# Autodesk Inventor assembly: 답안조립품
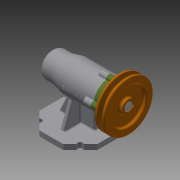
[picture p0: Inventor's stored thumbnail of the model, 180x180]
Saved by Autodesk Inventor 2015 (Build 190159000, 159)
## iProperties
Created: 2019-12
Part Number: 답안조립품
Document SubType Name: Assembly
Designer: 101548
Author: 101548
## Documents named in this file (12)
- C:\Users\101548\Desktop\491204V1047\답안조립품.iam
- C:\Users\101548\Desktop\491204V1047\V벨트풀리.ipt
- C:\Users\101548\Desktop\491204V1047\멈춤나사 M3.ipt
- C:\Users\101548\Desktop\491204V1047\베어링 6004.ipt
- C:\Users\101548\Desktop\491204V1047\베어링 51202.ipt
- C:\Users\101548\Desktop\491204V1047\본체.ipt
- C:\Users\101548\Desktop\491204V1047\볼트 M4.ipt
- C:\Users\101548\Desktop\491204V1047\어댑터슬리브.ipt
- C:\Users\101548\Desktop\491204V1047\오일 실.ipt
- C:\Users\101548\Desktop\491204V1047\축.ipt
- C:\Users\101548\Desktop\491204V1047\커버.ipt
- C:\Users\101548\Desktop\491204V1047\키 5 x 5 x 16.ipt
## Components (1 placed, 1 different names)
1. V벨트풀리:1 — 각도:2
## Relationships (1: Angle 1)
- 각도:2 [Angle]: V벨트풀리:1
